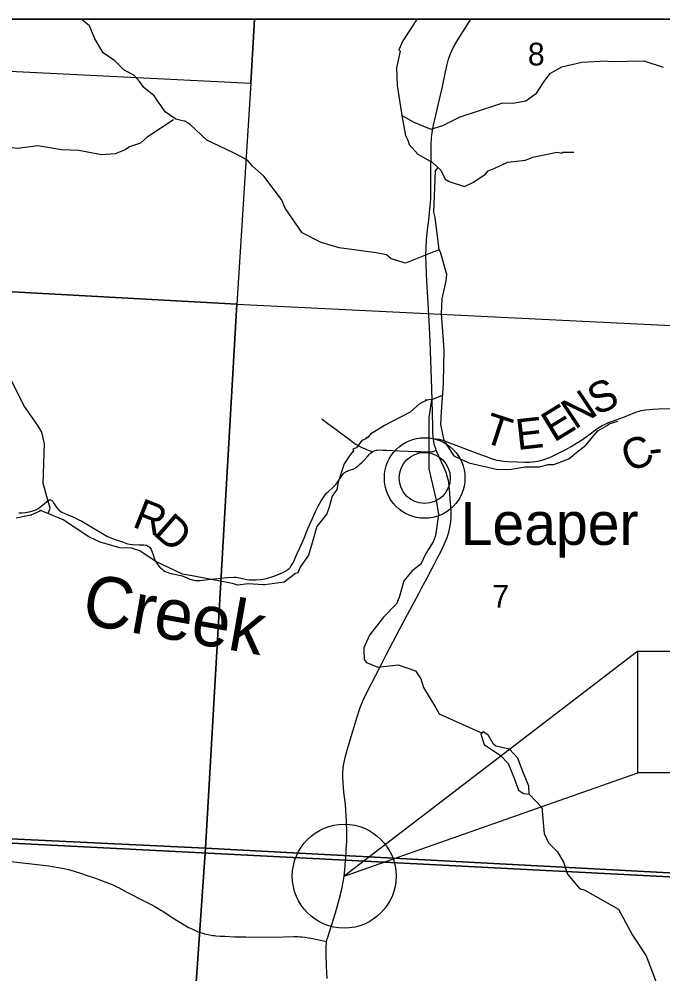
# Model space of a CAD drawing. Extents: x 0 to 34, y 0 to 22.
# Drawn here: x 4.884 to 6.074, y 19.136 to 20.9 of the extents above; entities that cross this region are included whole.
import ezdxf

# ---------------------------------------------------------------- set-up
doc = ezdxf.new("R2010")
doc.units = 0
for name, color, linetype in [('Default', 7, 'Continuous'), ('GM_X_County_Road', 7, 'Continuous'), ('GM_X_County_Road_Text', 7, 'Continuous'), ('GM_X_Minor_River', 7, 'Continuous'), ('GM_X_Minor_River_Text', 7, 'Continuous'), ('GM_X_Section', 7, 'Continuous'), ('GM_X_Section_Text', 7, 'Continuous'), ('GM_X_State_Route', 7, 'Continuous'), ('GM_X_Township_Road', 7, 'Continuous'), ('GM_X_Unincorporated', 7, 'Continuous'), ('GM_X_Unincorporated_Location', 7, 'Continuous'), ('GM_X_Unincorporated_Text', 7, 'Continuous'), ('SH_Cut_Line', 7, 'Continuous'), ('SH_Data', 7, 'Continuous'), ('TX_P_1', 7, 'Continuous')]:
    doc.layers.add(name, color=color, linetype=linetype)

msp = doc.modelspace()

# ---------------------------------------------------------------- linework, layer by layer
at = {"layer": 'Default'}
for points in [[(6.3694, 20.9), (2.1, 20.9)], [(4.7013, 19.3856), (5.4875, 19.3459), (6.2536, 19.3066)]]:
    msp.add_lwpolyline(points, dxfattribs=at)
for points in [[(5.3193, 20.9), (4.2645, 20.9), (4.26, 20.834), (5.3122, 20.7819)], [(6.3675, 20.9), (5.3193, 20.9), (5.3122, 20.7819), (5.2865, 20.3733), (6.3282, 20.3221)], [(2.1, 19.5179), (2.1, 14.1), (5.687, 14.1), (5.785, 14.1504), (5.9145, 14.1963), (5.9273, 14.1959), (5.9341, 14.3014), (6.0001, 15.328), (6.0418, 15.9539), (6.0633, 16.2368), (6.0901, 16.6706), (6.1151, 17.0743), (6.1723, 18.0255), (6.1917, 18.3385), (6.2282, 18.9116), (6.2536, 19.3066), (5.4875, 19.3459), (4.7013, 19.3856), (4.4284, 19.3984), (3.7007, 19.4348)]]:
    msp.add_lwpolyline(points, close=True, dxfattribs=at)
at = {"layer": 'GM_X_County_Road'}
for points in [[(5.65, 20.1245), (5.6542, 20.1242), (5.6581, 20.1239), (5.6603, 20.1236), (5.6626, 20.1231), (5.6668, 20.1218), (5.6748, 20.1189), (5.6961, 20.111), (5.7305, 20.098), (5.7494, 20.0909), (5.7567, 20.0883), (5.7628, 20.0864), (5.7675, 20.0852), (5.7724, 20.0842), (5.7794, 20.0832), (5.7871, 20.0825), (5.8048, 20.0817), (5.8198, 20.0815), (5.8276, 20.0815), (5.8334, 20.0818), (5.8382, 20.0823), (5.8433, 20.0832), (5.8482, 20.0843), (5.8529, 20.0856), (5.858, 20.0873), (5.8649, 20.0902), (5.8713, 20.0931), (5.8834, 20.0989), (5.8945, 20.1045), (5.9046, 20.1101), (5.9145, 20.1162), (5.9219, 20.121), (5.9278, 20.1251), (5.9373, 20.132), (5.9446, 20.1376), (5.9518, 20.1428), (5.9571, 20.1462), (5.962, 20.149), (5.9676, 20.1518), (5.9733, 20.1543), (5.9809, 20.1571), (6.0003, 20.164), (6.0177, 20.1711), (6.026, 20.1741), (6.0302, 20.1755), (6.034, 20.1766), (6.038, 20.1774), (6.042, 20.1781), (6.0488, 20.1788), (6.0558, 20.1792), (6.066, 20.1797), (6.0974, 20.1806)], [(5.3872, 19.8897), (5.3884, 19.8914), (5.3902, 19.8947), (5.3923, 19.8989), (5.395, 19.9055), (5.3979, 19.9123), (5.403, 19.9227), (5.4107, 19.9407), (5.4162, 19.9538), (5.4222, 19.968), (5.4255, 19.976), (5.4288, 19.9834), (5.4319, 19.9902), (5.437, 20.0001), (5.4426, 20.0097), (5.4462, 20.0155), (5.4486, 20.019), (5.4498, 20.0207), (5.4511, 20.0222), (5.4524, 20.0238), (5.4537, 20.0251), (5.4551, 20.0263), (5.4644, 20.0349), (5.4668, 20.0374), (5.4693, 20.0402), (5.473, 20.0451), (5.4786, 20.0534), (5.4811, 20.0568), (5.483, 20.0592), (5.4843, 20.0608), (5.4856, 20.0619), (5.4871, 20.063), (5.4887, 20.064), (5.4904, 20.0648), (5.4923, 20.0656), (5.5011, 20.0684), (5.5028, 20.0691), (5.5046, 20.0701), (5.5059, 20.0709), (5.5072, 20.0718), (5.5102, 20.074), (5.5142, 20.0776), (5.518, 20.0813), (5.521, 20.0844), (5.5278, 20.0916), (5.5319, 20.0961), (5.5338, 20.0977), (5.5356, 20.0991), (5.5379, 20.1005)], [(5.5379, 20.1005), (5.539, 20.1013), (5.5406, 20.1021), (5.5422, 20.1027), (5.544, 20.1032), (5.5461, 20.1036), (5.5494, 20.1038), (5.5562, 20.1037), (5.563, 20.1035), (5.5874, 20.1023), (5.6175, 20.101), (5.6261, 20.1007), (5.6374, 20.1003), (5.6406, 20.1003), (5.6437, 20.1003), (5.6468, 20.1007), (5.6493, 20.1012), (5.6517, 20.102), (5.6552, 20.1032)], [(4.8835, 19.9874), (4.8893, 19.9876), (4.8955, 19.9883), (4.9029, 19.9896), (4.9096, 19.9913), (4.9118, 19.992), (4.9141, 19.9929), (4.9163, 19.9939), (4.9182, 19.9951), (4.9218, 19.9975), (4.9308, 20.0047), (4.938, 20.0106), (4.9389, 20.0111), (4.94, 20.0114), (4.9411, 20.0116), (4.9422, 20.0116), (4.9433, 20.0112), (4.9444, 20.0106), (4.9452, 20.0099), (4.9461, 20.0088), (4.9488, 20.0042), (4.9526, 19.9985), (4.9554, 19.9951), (4.9581, 19.9925), (4.9616, 19.9898), (4.9643, 19.9882), (4.9671, 19.9868), (4.9729, 19.9845), (4.9804, 19.9816), (4.9849, 19.9797), (4.9933, 19.9755), (5.0001, 19.972), (5.0064, 19.9685), (5.0217, 19.9595), (5.0381, 19.9494), (5.0444, 19.9458), (5.0477, 19.944), (5.051, 19.9425), (5.0549, 19.941), (5.0651, 19.9373), (5.0767, 19.9332), (5.0827, 19.9312), (5.0853, 19.9305), (5.0882, 19.93), (5.0938, 19.9293), (5.1056, 19.9287), (5.1149, 19.9283), (5.1178, 19.928), (5.1197, 19.9276), (5.1212, 19.9269), (5.1227, 19.9262), (5.1243, 19.9251), (5.1257, 19.9237), (5.127, 19.9219), (5.1281, 19.9198), (5.1293, 19.917), (5.1319, 19.9098), (5.134, 19.904), (5.1362, 19.8986), (5.1385, 19.8944), (5.1407, 19.8913), (5.143, 19.8885), (5.1455, 19.8858), (5.1482, 19.8833), (5.1511, 19.8811), (5.1539, 19.8794), (5.1574, 19.8779), (5.1611, 19.8766), (5.1654, 19.8755), (5.1833, 19.8716), (5.1871, 19.8705), (5.1908, 19.869), (5.1959, 19.8668), (5.1997, 19.8653), (5.2028, 19.8642), (5.2063, 19.8633), (5.2103, 19.8629), (5.2141, 19.8626), (5.218, 19.8626), (5.2228, 19.863), (5.2379, 19.8648), (5.2449, 19.8659), (5.2506, 19.8664), (5.269, 19.868), (5.2818, 19.8688), (5.2852, 19.8687), (5.2887, 19.8682), (5.2994, 19.8656), (5.3053, 19.8645), (5.31, 19.864), (5.3146, 19.8639), (5.3222, 19.864), (5.33, 19.8645), (5.3347, 19.8651), (5.339, 19.866), (5.3432, 19.8671), (5.3514, 19.8695), (5.3567, 19.8715), (5.361, 19.8732), (5.3658, 19.8751), (5.3738, 19.8785), (5.3765, 19.8799), (5.3789, 19.8812), (5.381, 19.8827), (5.383, 19.8846), (5.3849, 19.8866), (5.3866, 19.8888), (5.3872, 19.8897)]]:
    msp.add_lwpolyline(points, dxfattribs=at)
at = {"layer": 'GM_X_Minor_River'}
for points in [[(5.6598, 20.4735), (5.5986, 20.4489), (5.572, 20.4573), (5.5632, 20.4644), (5.5444, 20.4681), (5.4755, 20.4775), (5.4425, 20.4873), (5.4072, 20.5048), (5.376, 20.5509), (5.3689, 20.5664), (5.3366, 20.6099), (5.3152, 20.6281), (5.3065, 20.6394), (5.2793, 20.6535), (5.2309, 20.6763), (5.2, 20.7054), (5.1904, 20.7111), (5.1859, 20.712), (5.1735, 20.715), (5.1542, 20.7289), (5.1336, 20.7581), (5.1148, 20.7739), (5.1068, 20.7844), (5.0962, 20.7965), (5.0776, 20.8062), (5.0611, 20.8227), (5.0392, 20.8378), (5.0241, 20.8637), (5.0143, 20.8876), (4.9985, 20.9)], [(5.6194, 20.9), (5.6189, 20.8984), (5.5936, 20.8596), (5.5861, 20.8429), (5.5884, 20.841), (5.5816, 20.8098), (5.5832, 20.7771), (5.5919, 20.7182), (5.5984, 20.6848), (5.6025, 20.6764), (5.6052, 20.6684), (5.6211, 20.6502), (5.6438, 20.6377), (5.6476, 20.6354), (5.6635, 20.6207), (5.6714, 20.6043), (5.679, 20.5998), (5.7073, 20.5907), (5.7225, 20.598), (5.7463, 20.6132), (5.7512, 20.6197), (5.7633, 20.6247), (5.7871, 20.6354), (5.8199, 20.6393), (5.8339, 20.645), (5.8789, 20.6542), (5.8846, 20.6531), (5.888, 20.652), (5.8887, 20.6543), (5.9095, 20.6543)], [(5.5925, 20.7212), (5.6137, 20.7097), (5.6454, 20.6969), (5.6672, 20.7034), (5.6994, 20.7195), (5.767, 20.7413), (5.778, 20.7451), (5.7969, 20.7445), (5.8205, 20.7491), (5.8402, 20.7629), (5.8556, 20.7863), (5.8662, 20.8), (5.8874, 20.8119), (5.9243, 20.8206), (5.969, 20.8226), (5.9773, 20.8219), (6.0389, 20.823), (6.0745, 20.8112)], [(5.1693, 20.7136), (5.1207, 20.6818), (5.1086, 20.6708), (5.088, 20.6642), (5.0799, 20.6584), (5.0619, 20.651), (5.0362, 20.6491), (4.9945, 20.6573), (4.9624, 20.6587), (4.9187, 20.6658), (4.8808, 20.6606), (4.8522, 20.6645), (4.7872, 20.7023), (4.7472, 20.6933), (4.6778, 20.6864), (4.6325, 20.6863), (4.6261, 20.6877), (4.6067, 20.6951)], [(5.658, 20.6258), (5.6529, 20.6199), (5.6501, 20.543)], [(5.6501, 20.543), (5.6526, 20.5332), (5.6598, 20.4735), (5.6625, 20.4701), (5.6743, 20.4287), (5.6731, 20.4162), (5.6652, 20.3831), (5.6645, 20.3557), (5.6695, 20.2888), (5.668, 20.2287), (5.6677, 20.2253), (5.6643, 20.1747), (5.6628, 20.1508), (5.6689, 20.1215), (5.6875, 20.0931), (5.7155, 20.0798), (5.7691, 20.0678), (5.7941, 20.0682), (5.8198, 20.0725), (5.8459, 20.0725), (5.8618, 20.0767), (5.8723, 20.0771), (5.9003, 20.0875), (5.915, 20.1), (5.9316, 20.1126), (5.9539, 20.1393), (5.9713, 20.1488), (5.9751, 20.1523), (5.9906, 20.1572)], [(4.9377, 19.9864), (4.9415, 19.9965), (4.9287, 20.042), (4.9309, 20.1149), (4.9258, 20.1369), (4.9189, 20.149), (4.8929, 20.1857), (4.8491, 20.274), (4.8387, 20.2864), (4.7873, 20.3238), (4.7723, 20.345), (4.7549, 20.3988)], [(5.6663, 20.2042), (5.648, 20.1971), (5.6348, 20.1956), (5.6375, 20.1956), (5.6242, 20.1891), (5.6069, 20.1738), (5.5596, 20.149), (5.5336, 20.133), (5.5275, 20.1254), (5.526, 20.1273), (5.5249, 20.1242), (5.5173, 20.1215), (5.5075, 20.1075), (5.5011, 20.1055), (5.5022, 20.1021), (5.4966, 20.0957), (5.4947, 20.093), (5.4852, 20.0781), (5.4736, 20.0443), (5.4713, 20.031), (5.4626, 20.0184), (5.457, 19.9979), (5.4532, 19.9861), (5.4343, 19.9625), (5.426, 19.932), (5.4189, 19.9092), (5.4034, 19.8875), (5.3993, 19.8768), (5.3951, 19.8753), (5.3743, 19.8593), (5.338, 19.8547), (5.3354, 19.8547), (5.3074, 19.8565), (5.2881, 19.8542), (5.2787, 19.8568), (5.2042, 19.8714), (5.1861, 19.8744), (5.1358, 19.8983), (5.107, 19.9172), (5.0915, 19.9225), (5.0703, 19.9232), (5.034, 19.9334), (5.0128, 19.9432), (4.9656, 19.9747), (4.9224, 19.9928), (4.9225, 19.9905), (4.9054, 19.9833), (4.9028, 19.9829), (4.8786, 19.9779)], [(5.6465, 20.1969), (5.6414, 20.1638), (5.6414, 20.1015), (5.6412, 20.0689), (5.6553, 20.0111), (5.6591, 19.9848), (5.6537, 19.9458), (5.6496, 19.9338), (5.6361, 19.9126), (5.6268, 19.8927), (5.6106, 19.8807), (5.5953, 19.8622), (5.5864, 19.831), (5.5815, 19.8194), (5.5577, 19.7951), (5.5318, 19.7617), (5.5216, 19.7381), (5.5215, 19.7332), (5.5221, 19.7168), (5.5261, 19.711), (5.547, 19.7024), (5.5845, 19.7069), (5.6167, 19.6956), (5.6265, 19.6808), (5.6316, 19.6647), (5.6547, 19.6272), (5.6604, 19.616), (5.7399, 19.5806)], [(5.7438, 19.5598), (5.7741, 19.5394), (5.7884, 19.5242), (5.7993, 19.4972), (5.8074, 19.4753), (5.8166, 19.4693), (5.8268, 19.4679), (5.8265, 19.4823), (5.8142, 19.5127), (5.8057, 19.5346), (5.7904, 19.5511), (5.7656, 19.5564), (5.7608, 19.56), (5.7518, 19.5762), (5.7426, 19.583), (5.7379, 19.5789), (5.7438, 19.5598)], [(5.8268, 19.4679), (5.8506, 19.4432), (5.8548, 19.3952), (5.8626, 19.3779), (5.8791, 19.361), (5.8906, 19.342), (5.8979, 19.3198), (5.9198, 19.2936), (5.9301, 19.2902)], [(5.9301, 19.2902), (5.992, 19.2553), (6.0181, 19.2072), (6.0434, 19.169), (6.0635, 19.1155), (6.0738, 19.0446), (6.08, 19.0188), (6.0877, 19.0025)]]:
    msp.add_lwpolyline(points, dxfattribs=at)
at = {"layer": 'GM_X_Section'}
for points in [[(4.26, 20.834), (5.3122, 20.7819), (5.2865, 20.3733), (4.2327, 20.4311)], [(4.2301, 20.4313), (4.2327, 20.4311), (5.2865, 20.3733), (5.2288, 19.368), (4.1716, 19.4188)], [(5.2865, 20.3733), (6.3282, 20.3221), (6.2595, 19.3129), (5.2288, 19.368)], [(4.1716, 19.4188), (5.2288, 19.368), (5.1578, 18.3486), (4.1036, 18.4009)], [(5.2288, 19.368), (6.2595, 19.3129), (6.1942, 18.2962), (5.1578, 18.3486)]]:
    msp.add_lwpolyline(points, close=True, dxfattribs=at)
at = {"layer": 'GM_X_State_Route'}
for points in [[(5.4877, 19.3454), (5.4879, 19.3487), (5.4888, 19.3656), (5.4896, 19.3812), (5.4897, 19.3992), (5.4892, 19.4173), (5.4879, 19.4383), (5.4871, 19.449), (5.4845, 19.4715), (5.483, 19.4892), (5.4826, 19.499), (5.4826, 19.5073), (5.4833, 19.5151), (5.484, 19.5208), (5.4851, 19.5267), (5.4875, 19.5379), (5.4915, 19.5532), (5.4945, 19.5637), (5.5088, 19.6104), (5.5148, 19.628), (5.5201, 19.6412), (5.5268, 19.6559), (5.5519, 19.7044), (5.5627, 19.7253), (5.588, 19.7731), (5.5936, 19.7838), (5.6023, 19.8), (5.6228, 19.8383), (5.6282, 19.8482), (5.6383, 19.8674), (5.6473, 19.8843), (5.652, 19.8937), (5.6551, 19.8998), (5.6582, 19.9058), (5.6634, 19.9157), (5.6662, 19.9211), (5.6699, 19.9289), (5.6738, 19.938), (5.6753, 19.9418), (5.6765, 19.9455), (5.6789, 19.9547), (5.681, 19.9639), (5.6816, 19.9679), (5.682, 19.9713), (5.6827, 19.9803), (5.6825, 19.9919), (5.6812, 20.013), (5.6803, 20.0236), (5.6789, 20.0377), (5.6783, 20.0425), (5.6776, 20.0471), (5.6768, 20.0508), (5.6756, 20.0554), (5.6733, 20.0624), (5.6698, 20.0708), (5.6605, 20.0908), (5.6592, 20.0936), (5.6567, 20.0992), (5.6552, 20.1032), (5.6536, 20.1075), (5.6522, 20.112), (5.6507, 20.1191), (5.65, 20.1245), (5.6494, 20.1286), (5.649, 20.1342), (5.6488, 20.1464), (5.6481, 20.1717), (5.6468, 20.2171), (5.6437, 20.3042), (5.6418, 20.3427), (5.6373, 20.4277), (5.6364, 20.4505), (5.6362, 20.4586), (5.6361, 20.4632), (5.6366, 20.4772), (5.6374, 20.492), (5.6393, 20.5104), (5.6407, 20.5237), (5.6419, 20.535), (5.6433, 20.5491), (5.6438, 20.5537), (5.6449, 20.5679), (5.645, 20.5743), (5.6453, 20.5982), (5.6452, 20.6234), (5.6455, 20.648), (5.6459, 20.6681), (5.6465, 20.6808), (5.6476, 20.6907), (5.65, 20.7041), (5.6542, 20.7222), (5.6596, 20.7439), (5.6661, 20.7724), (5.6725, 20.8028), (5.6755, 20.8161), (5.678, 20.8257), (5.681, 20.8344), (5.6845, 20.843), (5.6896, 20.8525), (5.697, 20.8648), (5.7085, 20.8832), (5.7192, 20.9)], [(4.869, 19.3434), (4.9232, 19.3371), (4.9392, 19.3351), (4.9526, 19.3329), (4.9675, 19.3302), (4.9781, 19.3277), (4.9877, 19.3248), (4.9977, 19.3217), (5.01, 19.3178), (5.0213, 19.3139), (5.0332, 19.3097), (5.0443, 19.3054), (5.053, 19.3019), (5.0586, 19.2995), (5.0636, 19.2972), (5.0688, 19.2947), (5.0834, 19.287), (5.117, 19.2693), (5.1294, 19.263), (5.1362, 19.2595), (5.1414, 19.2564), (5.1461, 19.2535), (5.1515, 19.2501), (5.1672, 19.2397), (5.1921, 19.2246), (5.1973, 19.2217), (5.2006, 19.22), (5.2043, 19.2181), (5.2087, 19.2162), (5.2148, 19.2137), (5.2188, 19.2123), (5.2228, 19.2111), (5.2269, 19.2098), (5.2306, 19.2089), (5.2335, 19.2083), (5.2361, 19.2078), (5.2388, 19.2073), (5.2417, 19.2068), (5.2453, 19.2064), (5.2479, 19.2061), (5.2556, 19.2056), (5.2643, 19.2051), (5.282, 19.2042), (5.3034, 19.2039), (5.353, 19.2036), (5.3921, 19.2047), (5.3957, 19.2047), (5.3994, 19.2046), (5.4031, 19.2043), (5.4068, 19.204), (5.413, 19.2033), (5.4184, 19.2024), (5.4233, 19.2015), (5.4413, 19.1978), (5.4525, 19.1955)], [(5.4525, 19.1955), (5.4532, 19.1986), (5.454, 19.2015), (5.4582, 19.2153), (5.4687, 19.2484), (5.474, 19.2665), (5.4782, 19.2826), (5.4813, 19.2954), (5.4833, 19.3054), (5.4851, 19.3163), (5.4863, 19.3281), (5.4877, 19.3454)], [(5.4533, 19.1272), (5.4525, 19.1496), (5.4519, 19.1735), (5.4519, 19.1871), (5.4521, 19.1921), (5.4525, 19.1955)]]:
    msp.add_lwpolyline(points, dxfattribs=at)
at = {"layer": 'GM_X_Township_Road'}
msp.add_lwpolyline([(5.4436, 20.1612), (5.4548, 20.1529), (5.4653, 20.1451), (5.4808, 20.1339), (5.4915, 20.1258), (5.5023, 20.1176), (5.5074, 20.1141), (5.5111, 20.1118), (5.5154, 20.1094), (5.5187, 20.1078), (5.5223, 20.1063), (5.526, 20.1048), (5.5379, 20.1005)], dxfattribs=at)
at = {"layer": 'GM_X_Unincorporated'}
for radius in [0.0744, 0.0472]:
    msp.add_circle((5.6338, 20.0521), radius, dxfattribs=at)
at = {"layer": 'GM_X_Unincorporated_Location'}
msp.add_line((5.6338, 20.0521), (5.6338, 20.0521), dxfattribs=at)
at = {"layer": 'SH_Cut_Line'}
msp.add_lwpolyline([(8.9, 14.1), (8.9, 20.9), (2.1, 20.9), (2.1, 14.1)], dxfattribs=at)
at = {"layer": 'SH_Data'}
msp.add_line((2.1, 20.9), (8.9, 20.9), dxfattribs=at)
at = {"layer": 'TX_P_1'}
for points in [[(6.0281, 19.7319), (5.4851, 19.3163), (6.0281, 19.5074)], [(6.0281, 19.7319), (7.3634, 19.7319), (7.3634, 19.5074), (6.0281, 19.5074)]]:
    msp.add_lwpolyline(points, close=True, dxfattribs=at)
msp.add_circle((5.4851, 19.3163), 0.096, dxfattribs=at)

# ---------------------------------------------------------------- texts
at = {"layer": 'GM_X_County_Road_Text'}
for s, rotation, p in [('S', 23.6824, (5.9507, 20.1671)), ('N', 33.8168, (5.9114, 20.1405)), ('E', 31.3233, (5.8729, 20.117)), ('T', 341.992, (5.7388, 20.1194)), ('E', 6.3632, (5.8052, 20.1036)), ('C', 21.0284, (6.0108, 20.0622)), ('-', 6.6661, (6.0507, 20.078)), ('R', 338.3562, (5.0913, 19.9628)), ('D', 318.7764, (5.1304, 19.9482))]:
    msp.add_text(s, height=0.0568, rotation=rotation, dxfattribs=at).set_placement(p)
at = {"layer": 'GM_X_Minor_River_Text'}
msp.add_text('Creek', height=0.0947, rotation=349.9986, dxfattribs=at).set_placement((4.9969, 19.7832))
at = {"layer": 'GM_X_Section_Text'}
for s, p in [('8', (5.8245, 20.8144)), ('7', (5.7587, 19.8124))]:
    msp.add_text(s, height=0.0419, rotation=0, dxfattribs=at).set_placement(p)
at = {"layer": 'GM_X_Unincorporated_Text'}
msp.add_text('Leaper', height=0.07898, rotation=0, dxfattribs=at).set_placement((5.7003, 19.9284))

doc.saveas('drawing.dxf')
